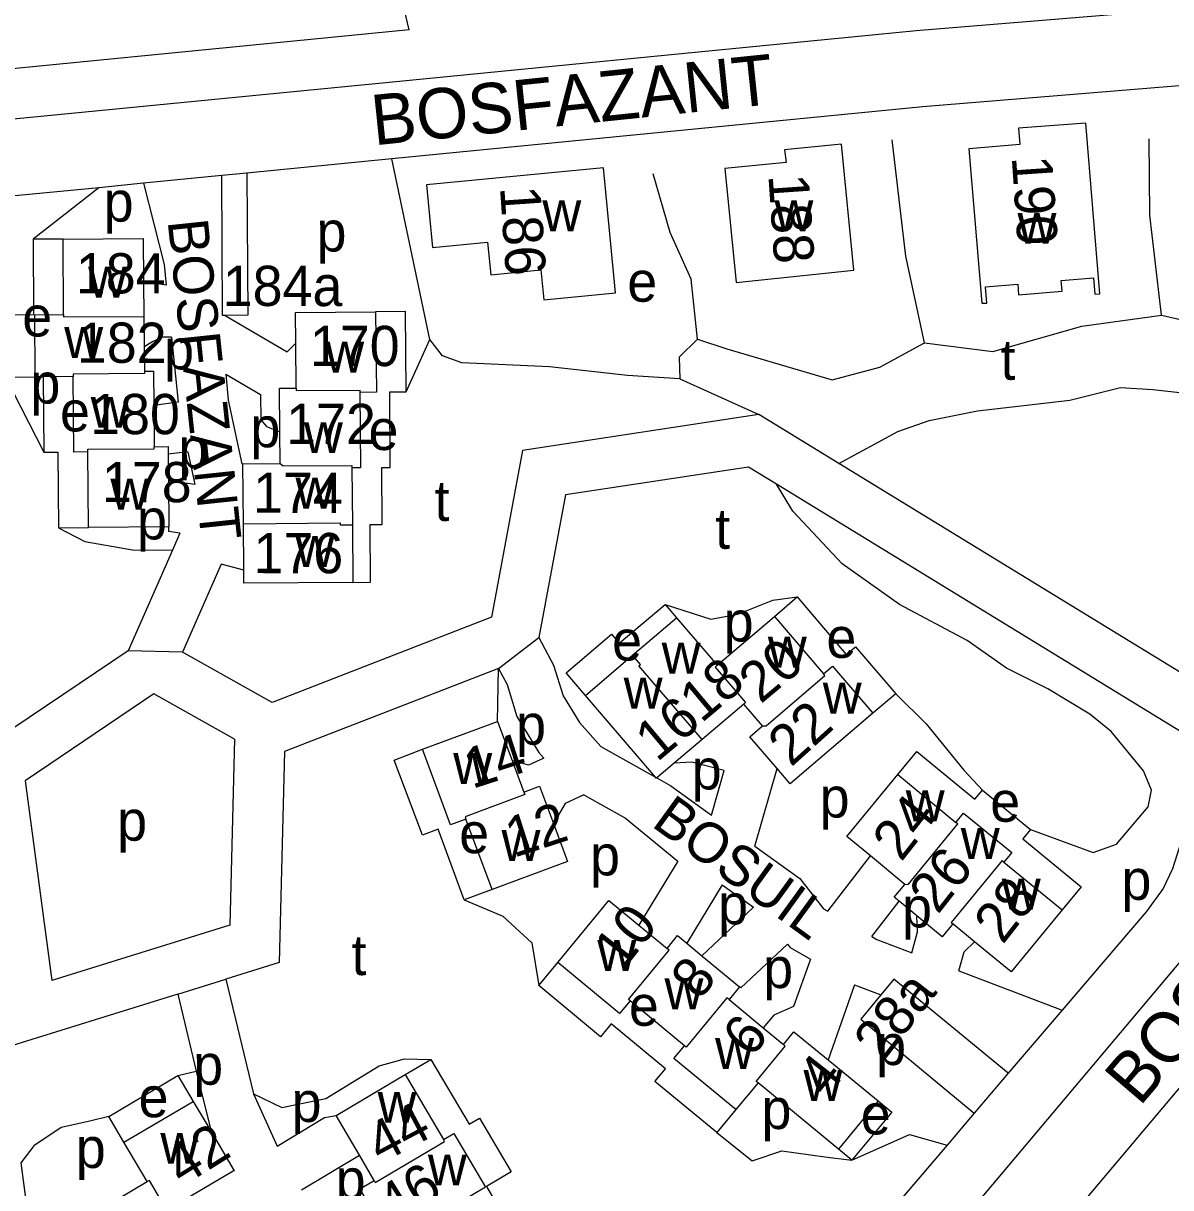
# Model space of a CAD drawing. Extents: x 155854 to 157362, y 383621 to 384685.
# Drawn here: x 156920.8 to 157034.9, y 383814.5 to 383930.2 of the extents above; entities that cross this region are included whole.
import ezdxf

# ---------------------------------------------------------------- set-up
doc = ezdxf.new("R2010")
doc.units = 0
for name, color, linetype in [('BLT_Basislijn', 7, 'Continuous'), ('BLT_Bebouwing', 7, 'Continuous'), ('BLT_Centroide', 7, 'Continuous'), ('BLT_Huisnummer', 7, 'Continuous'), ('BLT_Huisnummer_zonder_bebouwing', 7, 'Continuous'), ('BLT_Onderverdeling_panden', 7, 'Continuous'), ('BLT_Straatnaam', 7, 'Continuous'), ('BLT_Straatnaam_verkleind', 7, 'Continuous'), ('BLT_Vlakafsluiter', 7, 'Continuous')]:
    doc.layers.add(name, color=color, linetype=linetype)

msp = doc.modelspace()

# ---------------------------------------------------------------- linework, layer by layer
at = {"layer": 'BLT_Basislijn'}
for p, q in [((156959.19, 383929.54), (156957.23, 383937.68)), ((156957.44, 383916.71), (156943.03, 383915.29)), ((156961.23, 383898.76), (156957.44, 383916.71)), ((156940.54, 383915.05), (156932.76, 383914.29)), ((156943.03, 383915.29), (156940.54, 383915.05)), ((156940.63, 383901.16), (156940.54, 383915.05)), ((156928.32, 383913.85), (156878.09, 383908.93)), ((156928.32, 383913.85), (156921.79, 383908.72)), ((156932.76, 383914.29), (156928.32, 383913.85)), ((156924.77, 383908.74), (156921.79, 383908.72)), ((156935.02, 383904.17), (156932.78, 383904.53)), ((156940.87, 383901.16), (156940.63, 383901.16)), ((156935.54, 383899.01), (156936.2, 383892.52)), ((156958.88, 383893.56), (156961.23, 383898.76)), ((156919.04, 383895.02), (156922.01, 383895.04)), ((156919.04, 383895.02), (156922.86, 383887.56)), ((156922.81, 383895.05), (156922.86, 383887.56)), ((156986.07, 383894.87), (156993.95, 383891.31)), ((156936.2, 383892.52), (156933.79, 383892.2)), ((157001.88, 383886.45), (156993.95, 383891.31)), ((156937.18, 383887.6), (156935.23, 383887.35)), ((156937.18, 383887.6), (156937.86, 383884.36)), ((157040.01, 383863.1), (157001.88, 383886.45)), ((156937.86, 383884.36), (156935.25, 383884.72)), ((157038.75, 383858.01), (156995.68, 383884.38)), ((156924.31, 383880.06), (156927.31, 383880.08)), ((156936.39, 383879.52), (156935.64, 383877.81)), ((156935.64, 383877.81), (156931.24, 383867.82)), ((156940.49, 383876.43), (156936.64, 383867.68)), ((156942.74, 383875.85), (156940.49, 383876.43)), ((156995.48, 383871.24), (156997.74, 383873.17)), ((156984.62, 383872.43), (156985.75, 383871.1)), ((156931.24, 383867.82), (156917.68, 383858.68)), ((156945.56, 383862.68), (156936.64, 383867.68)), ((156967.96, 383860.81), (156968.05, 383866.06)), ((157007.54, 383863.55), (157005.28, 383861.61)), ((156993.54, 383848.4), (156995.75, 383856.11)), ((157016.16, 383853.96), (157020.94, 383850.05)), ((156985.87, 383846.91), (156982.01, 383840.55)), ((157000.8, 383841.93), (157005.02, 383847.44)), ((156990.3, 383844.57), (156986.78, 383838.76)), ((156990.3, 383844.57), (156993.4, 383842.35)), ((156967.43, 383844.1), (156964.66, 383843.06)), ((156993.4, 383842.35), (156988.27, 383837.52)), ((157005.16, 383839.41), (157007.87, 383842.94)), ((157007.86, 383791.26), (157050.45, 383841.83)), ((156972.05, 383834.55), (156973.95, 383836.84)), ((156940.95, 383835.19), (156943.71, 383823.8)), ((157013.83, 383836.02), (157024.09, 383832.12)), ((157003.46, 383834.61), (157000.81, 383827.18)), ((157003.46, 383834.61), (157006.07, 383833.62)), ((156936.17, 383833.7), (156898.3, 383821.94)), ((156936.17, 383833.7), (156938.02, 383826.05)), ((157024.09, 383832.12), (157018.73, 383825.84)), ((156958.78, 383825.7), (156961.33, 383827.21)), ((156936.19, 383825.6), (156938.02, 383826.05)), ((156938.02, 383826.05), (156939.48, 383820.04)), ((157018.73, 383825.84), (157015.35, 383821.88)), ((156929.31, 383821.54), (156936.19, 383825.6)), ((156936.19, 383825.6), (156937.71, 383823.04)), ((156943.71, 383823.8), (156946.05, 383818.6)), ((156991.66, 383822.22), (156989.77, 383819.93)), ((156930.81, 383818.98), (156929.31, 383821.54)), ((157015.35, 383821.88), (157012.64, 383818.7)), ((156948.49, 383814.23), (156954.24, 383817.68)), ((157012.64, 383818.7), (156986.9, 383788.56)), ((157003.18, 383817.19), (157001.86, 383818.29))]:
    msp.add_line(p, q, dxfattribs=at)
for points in [[(157073.16, 383934.67), (157009.56, 383929.45), (157005.53, 383929.05)], [(156959.19, 383929.54), (156882.96, 383922.07)], [(157005.53, 383929.05), (156970.35, 383925.61)], [(156970.35, 383925.61), (156957.18, 383924.32)], [(157051.91, 383925.3), (157010.24, 383921.88), (156957.44, 383916.71)], [(156957.18, 383924.32), (156884.17, 383917.17)], [(157010.41, 383898.42), (157008.54, 383907.05), (157007.18, 383918.6)], [(157033.96, 383901.17), (157032.79, 383911.12), (157032.74, 383918.7)], [(156943.03, 383915.29), (156943.15, 383901.18), (156940.87, 383901.16)], [(156987.83, 383898.79), (156987.2, 383904.77), (156985.11, 383909.4), (156983.43, 383915.23)], [(156932.76, 383914.29), (156934.81, 383906.23), (156935.02, 383904.17)], [(156921.79, 383908.72), (156921.85, 383901.22), (156918.99, 383901.19), (156919.04, 383895.02)], [(157033.96, 383901.17), (157039.29, 383899.94), (157043.88, 383900.08), (157047.73, 383901.55), (157054.45, 383902.42)], [(156940.87, 383901.16), (156947.04, 383897.55), (156947.9, 383898.41)], [(156958.88, 383893.56), (156958.82, 383901.54), (156955.84, 383901.52)], [(157010.41, 383898.42), (157017.21, 383897.58), (157026.04, 383900.1), (157033.96, 383901.17)], [(156935.54, 383899.01), (156934.74, 383899.01), (156934.51, 383898.97), (156933.65, 383898.52), (156932.84, 383898.03)], [(156986.07, 383894.87), (156980.87, 383895.17), (156973.14, 383896.06), (156964.41, 383896.45), (156962.48, 383897.13), (156961.23, 383898.76)], [(156987.83, 383898.79), (156986.01, 383897.02), (156986.07, 383894.87)], [(156987.83, 383898.79), (156990.77, 383897.84), (157001.22, 383894.74), (157005.96, 383896.03), (157010.41, 383898.42)], [(157001.88, 383886.45), (157007.75, 383889.61), (157010.87, 383890.72), (157015.68, 383891.69), (157024.85, 383892.75), (157029.88, 383893.98), (157033.09, 383893.8), (157041.14, 383892.89), (157045.63, 383892.86), (157048.98, 383894.37), (157051.3, 383896.38), (157057.73, 383898.14), (157058.58, 383899.27)], [(156940.94, 383895.32), (156941.2, 383892.75), (156942.54, 383886.4), (156942.65, 383886.4)], [(156940.94, 383895.32), (156944.41, 383893.29), (156944.44, 383890.79), (156945.01, 383890.12), (156946.33, 383889.6)], [(156953.58, 383874.62), (156955.34, 383874.63), (156955.3, 383880.36), (156956.49, 383880.37), (156956.46, 383886.04), (156957.29, 383886.04), (156957.24, 383893.55), (156958.88, 383893.56)], [(156993.95, 383891.31), (156970.44, 383887.73), (156967.36, 383871.16), (156945.56, 383862.68)], [(156922.86, 383887.56), (156924.26, 383887.57), (156924.31, 383880.06)], [(156995.68, 383884.38), (156992.9, 383886.09), (156974.71, 383883.32), (156972.07, 383869.14)], [(157020.94, 383850.05), (157027.17, 383847.78), (157029.5, 383848.6), (157032.62, 383852.3), (157032.97, 383853.97), (157032.17, 383855.89), (157028.97, 383859.79), (157026.84, 383861.52), (157022.66, 383864.05), (157018.56, 383866.11), (157014.65, 383868.83), (157007.93, 383872.43), (157002.22, 383876.48), (156997.31, 383881.7), (156995.68, 383884.38)], [(156924.31, 383880.06), (156926.95, 383878.7), (156931.66, 383877.86), (156935.64, 383877.81)], [(156936.39, 383879.52), (156935.28, 383879.67), (156935.28, 383880.16)], [(156984.62, 383872.43), (156989.15, 383870.97), (156991.84, 383871.48), (156995.33, 383872.86), (156997.74, 383873.17)], [(156997.74, 383873.17), (157002.6, 383867.44), (157003.53, 383868.23), (157007.54, 383863.55)], [(156976.71, 383863.38), (156974.79, 383865.64), (156979.29, 383869.49), (156980.06, 383868.58), (156984.62, 383872.43)], [(156972.07, 383869.14), (156973.54, 383866.41), (156974.49, 383863.36), (156976.1, 383860.7), (156978.23, 383858.3), (156983.65, 383855.26)], [(156968.05, 383866.06), (156946.8, 383857.8), (156946.27, 383836.84), (156940.95, 383835.19)], [(156968.05, 383866.06), (156968.91, 383864.46), (156969.89, 383861.3), (156972.06, 383857.71), (156972.55, 383857.16)], [(156941.83, 383859.03), (156933.81, 383863.53), (156921, 383854.89), (156923.67, 383835.06)], [(157007.54, 383863.55), (157010.58, 383860.56), (157014.32, 383855.95), (157016.16, 383853.96)], [(156941.83, 383859.03), (156941.36, 383840.55), (156923.67, 383835.06)], [(156964.66, 383843.06), (156962.05, 383850.08), (156960.51, 383849.51), (156957.67, 383856.95), (156960.49, 383858.03)], [(156972.55, 383857.16), (156971.03, 383856.45), (156969.41, 383856.91)], [(157007.75, 383855.53), (157009.64, 383857.82), (157015.41, 383853.06), (157016.16, 383853.96)], [(157038.75, 383858.01), (157038.51, 383857.02), (157035.06, 383846.15), (157034.13, 383844.19), (157032.44, 383841.89), (157024.09, 383832.12)], [(156989.22, 383851.5), (156990.5, 383855.94), (156987.27, 383856.76), (156985.53, 383856.65)], [(156983.81, 383855.18), (156985.18, 383854.41), (156989.22, 383851.5)], [(156976.55, 383853.52), (156974.69, 383852.65), (156973.51, 383850.67)], [(156976.55, 383853.52), (156980.67, 383851.2), (156985.87, 383846.91)], [(157020.94, 383850.05), (157020.18, 383849.12), (157025.97, 383844.36), (157024.09, 383842.07)], [(156993.54, 383848.4), (156998, 383845.2), (157000.37, 383842.18), (157000.8, 383841.93)], [(156964.66, 383843.06), (156968.49, 383841.44), (156971.38, 383838.78), (156972.05, 383834.55)], [(156962.53, 383762.57), (156964.14, 383762.14), (156966.02, 383761.85), (156967.12, 383761.85), (156968.88, 383761.99), (156970.37, 383762.24), (156971.36, 383762.6), (156972.39, 383763.09), (156973.75, 383763.9), (156974.95, 383764.82), (156975.94, 383765.78), (157039.24, 383840.94)], [(157009.14, 383837.8), (157009.71, 383839.89), (157009.63, 383841.49)], [(156996.78, 383838.66), (156992.15, 383834.31), (156992.02, 383834.42)], [(156996.78, 383838.66), (156997.04, 383838.33), (156999.06, 383837.16)], [(157005.16, 383839.41), (157005.67, 383839.12), (157009.14, 383837.8)], [(157013.83, 383836.02), (157014.35, 383837.91), (157015.36, 383838.91)], [(156999.06, 383837.16), (156997.39, 383832.47), (156995.43, 383831.61), (156994.38, 383830.34)], [(157018.73, 383825.84), (157007.37, 383835.19), (157006.07, 383833.62)], [(156989.77, 383819.93), (156983.61, 383825.02), (156984.65, 383826.28), (156979.25, 383830.74), (156978.19, 383829.47), (156972.05, 383834.55)], [(157006.07, 383833.62), (157004.09, 383831.21), (157015.35, 383821.88)], [(156943.71, 383823.8), (156946.53, 383822.43), (156950.88, 383823.34), (156956.18, 383826.57), (156958.72, 383827.27), (156961.33, 383827.21)], [(156961.33, 383827.21), (156965.14, 383820.76), (156966.16, 383821.36), (156969.31, 383816.03), (156966.86, 383814.59), (156970.38, 383808.5), (156971.84, 383809.34), (156975.88, 383802.49), (156974.46, 383801.66), (156978.28, 383795.2)], [(157005.8, 383823.08), (157007.17, 383821.96), (157003.18, 383817.19)], [(156929.31, 383821.54), (156927.43, 383821.08), (156924.6, 383820.45), (156921.87, 383818.62), (156920.58, 383816.92), (156921.16, 383812.41), (156924.11, 383809.75)], [(156946.05, 383818.6), (156950.76, 383821.42), (156951.91, 383821.65)], [(156989.77, 383819.93), (156993.26, 383817.14), (156996.22, 383818.11), (157000.48, 383817.54), (157003.18, 383817.19)], [(157003.18, 383817.19), (157008.91, 383819.75), (157012.64, 383818.7)]]:
    msp.add_lwpolyline(points, dxfattribs=at)
at = {"layer": 'BLT_Bebouwing'}
for p, q in [((156924.83, 383901.24), (156924.77, 383908.74)), ((156932.78, 383904.53), (156932.81, 383901.06)), ((156932.81, 383901.06), (156932.84, 383898.03)), ((156932.84, 383898.03), (156932.86, 383895.62)), ((156947.94, 383893.94), (156947.9, 383898.41)), ((156922.81, 383895.05), (156922.01, 383895.04)), ((156925.78, 383895.08), (156922.81, 383895.05)), ((156933.79, 383892.2), (156933.82, 383888.11)), ((156946.35, 383886.43), (156946.33, 383889.6)), ((156927.31, 383880.08), (156927.25, 383887.59)), ((156935.23, 383887.35), (156935.25, 383884.72)), ((156942.65, 383886.4), (156946.35, 383886.43)), ((156942.71, 383880.45), (156942.65, 383886.4)), ((156935.25, 383884.72), (156935.28, 383880.16)), ((156935.28, 383880.16), (156927.31, 383880.08)), ((156942.74, 383875.85), (156942.71, 383880.45)), ((156953.54, 383880.35), (156953.58, 383874.62)), ((156981.39, 383867.38), (156985.75, 383871.1)), ((156989.78, 383866.38), (156995.48, 383871.24)), ((156995.48, 383871.24), (157000.35, 383865.54)), ((156976.71, 383863.38), (156981.39, 383867.38)), ((156983.65, 383855.26), (156976.71, 383863.38)), ((156992.43, 383862.53), (156988.29, 383859)), ((156994.29, 383860.36), (156992.43, 383862.53)), ((156960.49, 383858.03), (156967.96, 383860.81)), ((156967.96, 383860.81), (156969.41, 383856.91)), ((156988.29, 383859), (156985.53, 383856.65)), ((156969.41, 383856.91), (156970.58, 383853.78)), ((156985.53, 383856.65), (156983.81, 383855.18)), ((157007.75, 383855.53), (157013.53, 383850.77)), ((156967.43, 383844.1), (156964.82, 383851.1)), ((157008.46, 383844.61), (157005.02, 383847.44)), ((157018.3, 383846.83), (157024.09, 383842.07)), ((157009.63, 383841.49), (157007.87, 383842.94)), ((156982.01, 383840.55), (156984.81, 383838.23)), ((157015.36, 383838.91), (157013.22, 383840.67)), ((156986.78, 383838.76), (156988.27, 383837.52)), ((156988.27, 383837.52), (156992.02, 383834.42)), ((156992.02, 383834.42), (156990.97, 383833.16)), ((156986.54, 383828.56), (156981.15, 383833.03)), ((156990.97, 383833.16), (156994.38, 383830.34)), ((156994.38, 383830.34), (156996.37, 383828.69)), ((157000.81, 383827.18), (157005.8, 383823.08)), ((156951.91, 383821.65), (156958.78, 383825.7)), ((156958.78, 383825.7), (156962.58, 383819.24)), ((156993.86, 383824.87), (156991.66, 383822.22)), ((157001.86, 383818.29), (156993.86, 383824.87)), ((156930.81, 383818.98), (156937.71, 383823.04)), ((156937.71, 383823.04), (156939.48, 383820.04)), ((157005.8, 383823.08), (157001.86, 383818.29)), ((156954.24, 383817.68), (156951.91, 383821.65)), ((156933.12, 383815.06), (156930.81, 383818.98)), ((156955.71, 383815.18), (156954.24, 383817.68)), ((156941.68, 383816.1), (156935.29, 383812.34)), ((156926.66, 383811.25), (156933.12, 383815.06))]:
    msp.add_line(p, q, dxfattribs=at)
for points in [[(157026.44, 383920.28), (157019.74, 383919.76), (157019.87, 383918.15), (157014.82, 383917.72), (157016.11, 383902.36), (157016.59, 383902.39), (157016.46, 383903.99), (157019.67, 383904.25), (157019.76, 383903.2), (157024.08, 383903.56), (157023.99, 383904.62), (157027.21, 383904.88), (157027.34, 383903.27), (157027.82, 383903.31)], [(156991.67, 383904.42), (157003.39, 383905.64), (157002.16, 383918.17), (156996.5, 383917.63), (156996.64, 383916.36), (156990.56, 383915.77)], [(156978.49, 383915.84), (156960.9, 383914.12), (156961.5, 383907.91), (156966.97, 383908.44), (156967.28, 383905.19), (156972.27, 383905.68), (156972.55, 383902.7), (156979.68, 383903.39)]]:
    msp.add_lwpolyline(points, close=True, dxfattribs=at)
for points in [[(156924.77, 383908.74), (156932.74, 383908.81), (156932.78, 383904.53)], [(156922.01, 383895.04), (156921.96, 383901.22), (156924.83, 383901.24)], [(156947.9, 383898.41), (156947.87, 383901.44), (156955.84, 383901.52)], [(156955.84, 383901.52), (156955.93, 383893.54), (156954.27, 383893.51)], [(156932.86, 383895.62), (156933.76, 383895.62), (156933.79, 383892.2)], [(156927.25, 383887.59), (156925.85, 383887.58), (156925.78, 383895.08)], [(156946.33, 383889.6), (156946.29, 383893.92), (156947.94, 383893.94)], [(156954.27, 383893.51), (156954.34, 383886.02), (156953.49, 383886.01)], [(156933.82, 383888.11), (156935.22, 383888.14), (156935.23, 383887.35)], [(156953.49, 383886.01), (156953.54, 383880.35)], [(156953.58, 383874.62), (156942.75, 383874.53), (156942.74, 383875.85)], [(156985.75, 383871.1), (156986.53, 383870.18), (156989.78, 383866.38)], [(157000.35, 383865.54), (157001.26, 383866.31), (157005.28, 383861.61)], [(157005.28, 383861.61), (156997.05, 383854.59), (156995.75, 383856.11)], [(156995.75, 383856.11), (156993.04, 383859.28), (156994.29, 383860.36)], [(156964.82, 383851.1), (156963.28, 383850.54), (156960.49, 383858.03)], [(156983.81, 383855.18), (156983.76, 383855.14), (156983.65, 383855.26)], [(157005.02, 383847.44), (157002.67, 383849.38), (157007.75, 383855.53)], [(156970.58, 383853.78), (156972.13, 383854.36), (156973.51, 383850.67)], [(157013.53, 383850.77), (157014.28, 383851.69), (157019.07, 383847.76), (157018.3, 383846.83)], [(156973.51, 383850.67), (156974.93, 383846.89), (156967.43, 383844.1)], [(157007.87, 383842.94), (157007.4, 383843.33), (157008.46, 383844.61)], [(156973.95, 383836.84), (156979.03, 383843.02), (156982.01, 383840.55)], [(157024.09, 383842.07), (157019.01, 383835.9), (157015.36, 383838.91)], [(157013.22, 383840.67), (157012.17, 383839.4), (157009.63, 383841.49)], [(156984.81, 383838.23), (156985.86, 383839.51), (156986.78, 383838.76)], [(156981.15, 383833.03), (156980.09, 383831.76), (156973.95, 383836.84)], [(156996.37, 383828.69), (156997.43, 383829.96), (157000.81, 383827.18)], [(156991.66, 383822.22), (156985.5, 383827.3), (156986.54, 383828.56)], [(156939.48, 383820.04), (156941.77, 383816.15), (156941.68, 383816.1)], [(156962.58, 383819.24), (156963.61, 383819.85), (156966.75, 383814.52), (156964.3, 383813.07)], [(156955.23, 383812.74), (156954.28, 383814.34), (156955.71, 383815.18)]]:
    msp.add_lwpolyline(points, dxfattribs=at)
at = {"layer": 'BLT_Onderverdeling_panden'}
for points in [[(156924.83, 383901.24), (156924.83, 383901), (156932.81, 383901.06)], [(156932.86, 383895.62), (156932.86, 383895.38), (156925.78, 383895.33), (156925.78, 383895.08)], [(156947.94, 383893.94), (156947.94, 383893.68), (156954.27, 383893.74), (156954.27, 383893.51)], [(156927.25, 383887.59), (156927.25, 383887.86), (156933.82, 383887.91), (156933.82, 383888.11)], [(156946.35, 383886.43), (156946.64, 383886.2), (156953.49, 383886.25), (156953.49, 383886.01)], [(156942.71, 383880.45), (156952.33, 383880.53), (156952.33, 383880.34), (156953.54, 383880.35)], [(156988.29, 383859), (156982.02, 383866.34), (156982.17, 383866.46), (156981.39, 383867.38)], [(156989.78, 383866.38), (156989.59, 383866.21), (156992.61, 383862.68), (156992.43, 383862.53)], [(156994.29, 383860.36), (156994.65, 383860.38), (157000.5, 383865.37), (157000.35, 383865.54)], [(156970.58, 383853.78), (156970.67, 383853.53), (156964.74, 383851.33), (156964.82, 383851.1)], [(157008.46, 383844.61), (157008.81, 383844.63), (157013.73, 383850.61), (157013.53, 383850.77)], [(157018.3, 383846.83), (157018.12, 383846.98), (157013.04, 383840.82), (157013.22, 383840.67)], [(156981.15, 383833.03), (156980.97, 383833.18), (156985.01, 383838.06), (156984.81, 383838.23)], [(156990.97, 383833.16), (156990.77, 383833.32), (156986.71, 383828.42), (156986.54, 383828.56)], [(156993.86, 383824.87), (156993.66, 383825.03), (156996.56, 383828.53), (156996.37, 383828.69)], [(156955.71, 383815.18), (156955.81, 383814.99), (156962.7, 383819.04), (156962.58, 383819.24)], [(156935.29, 383812.34), (156935.09, 383812.23), (156933.35, 383815.19), (156933.12, 383815.06)]]:
    msp.add_lwpolyline(points, dxfattribs=at)
at = {"layer": 'BLT_Vlakafsluiter'}
for p, q in [((156968.05, 383866.06), (156972.07, 383869.14)), ((156936.64, 383867.68), (156931.24, 383867.82)), ((156936.17, 383833.7), (156940.95, 383835.19))]:
    msp.add_line(p, q, dxfattribs=at)

# ---------------------------------------------------------------- texts
at = {"layer": 'BLT_Centroide'}
for s, p in [('p', (156928.81, 383910.48)), ('w', (156972.42, 383909.53)), ('w', (156995.49, 383909.53)), ('w', (157019.65, 383908.28)), ('p', (156949.97, 383907.51)), ('w', (156927.27, 383902.92)), ('e', (156980.86, 383902.52)), ('e', (156920.72, 383899.06)), ('w', (156924.89, 383896.93)), ('p', (156934.82, 383895.79)), ('w', (156950.83, 383895.46)), ('t', (157017.96, 383894.76)), ('p', (156921.53, 383892.4)), ('w', (156927.52, 383889.99)), ('e', (156924.47, 383889.63)), ('p', (156943.39, 383888.05)), ('w', (156948.72, 383887.47)), ('e', (156955.14, 383887.78)), ('p', (156936.24, 383885.96)), ('w', (156929.48, 383881.86)), ('w', (156947.88, 383881.96)), ('t', (156961.69, 383880.73)), ('p', (156932.13, 383878.89)), ('t', (156989.59, 383877.96)), ('w', (156947.88, 383876.15)), ('p', (156990.44, 383868.75)), ('e', (156979.35, 383866.85)), ('e', (157000.65, 383867.12)), ('w', (156984.28, 383865.55)), ('w', (156994.83, 383866.14)), ('w', (156980.5, 383862.08)), ('w', (157000.29, 383861.59)), ('p', (156969.81, 383858.49)), ('w', (156963.56, 383854.58)), ('p', (156987.26, 383854.04)), ('p', (156999.98, 383851.25)), ('w', (157008.54, 383850.88)), ('e', (157016.94, 383850.83)), ('p', (156930.15, 383848.95)), ('e', (156964.15, 383847.71)), ('w', (156968.36, 383846.94)), ('w', (157014.01, 383847.13)), ('p', (156977.16, 383845.5)), ('p', (157029.98, 383843.07)), ('w', (157018.08, 383842.09)), ('p', (156989.89, 383840.63)), ('p', (157008.18, 383840.33)), ('t', (156953.44, 383835.59)), ('w', (156977.89, 383836)), ('p', (156994.37, 383834.3)), ('w', (156984.56, 383832.19)), ('e', (156981.02, 383830.55)), ('w', (156989.59, 383826.25)), ('p', (157005.6, 383826.65)), ('p', (156937.71, 383824.69)), ('w', (156998.38, 383823.08)), ('e', (156932.28, 383821.46)), ('p', (156947.49, 383820.99)), ('w', (156956.04, 383820.91)), ('p', (156994.2, 383820.29)), ('e', (157004.07, 383819.76)), ('w', (156934.44, 383816.84)), ('p', (156926.04, 383816.42)), ('w', (156961.04, 383814.68)), ('p', (156951.87, 383813.31))]:
    msp.add_text(s, height=4, dxfattribs=at).set_placement(p)
at = {"layer": 'BLT_Huisnummer'}
for s, rotation, p in [('190', 273.9241, (157019.07, 383916.91)), ('188', 273.9241, (156994.88, 383915.09)), ('186', 273.9241, (156968.2, 383913.9)), ('184', 359.9241, (156926.04, 383903.35)), ('182', 359.9241, (156926.14, 383896.45)), ('170', 359.9241, (156949.3, 383896.13)), ('180', 359.9241, (156927.46, 383889.36)), ('172', 359.9241, (156946.94, 383888.38)), ('178', 359.9241, (156928.63, 383882.6)), ('174', 359.9241, (156943.65, 383881.54)), ('176', 359.9241, (156943.7, 383875.54)), ('20', 39.9241, (156994.11, 383862.48)), ('18', 39.9241, (156988.21, 383860.57)), ('16', 39.9241, (156983.81, 383856.7)), ('22', 41.9241, (156997.13, 383856.2)), ('14', 17.9241, (156965.44, 383854.08)), ('12', 17.9241, (156969.57, 383847.24)), ('24', 51.9241, (157008.09, 383846.76)), ('26', 51.9241, (157011.73, 383841.54)), ('28', 51.9241, (157018.18, 383838.55)), ('10', 51.9241, (156980.36, 383835.88)), ('8', 51.9241, (156988.05, 383832.99)), ('6', 51.9241, (156993.2, 383827.25)), ('4', 51.9241, (157000.66, 383823.31)), ('44', 27.9241, (156956.34, 383816.81)), ('42', 31.9241, (156936.63, 383814.54)), ('46', 31.9241, (156957.62, 383810.64))]:
    msp.add_text(s, height=4, rotation=rotation, dxfattribs=at).set_placement(p)
at = {"layer": 'BLT_Huisnummer_zonder_bebouwing'}
for s, rotation, p in [('184a', 359.9241, (156940.64, 383902.1)), ('28a', 51.9241, (157006.23, 383826.85))]:
    msp.add_text(s, height=4, rotation=rotation, dxfattribs=at).set_placement(p)
at = {"layer": 'BLT_Straatnaam'}
for s, rotation, p in [('BOSFAZANT', 5.9224, (156955.68, 383918.05)), ('BOSUIL', 49.5329, (157031.78, 383822.44))]:
    msp.add_text(s, height=5, rotation=rotation, dxfattribs=at).set_placement(p)
at = {"layer": 'BLT_Straatnaam_verkleind'}
for s, rotation, p in [('BOSFAZANT', 276.0275, (156935.16, 383910.55)), ('BOSUIL', 324.0275, (156983.15, 383850.45))]:
    msp.add_text(s, height=4, rotation=rotation, dxfattribs=at).set_placement(p)

doc.saveas('drawing.dxf')
